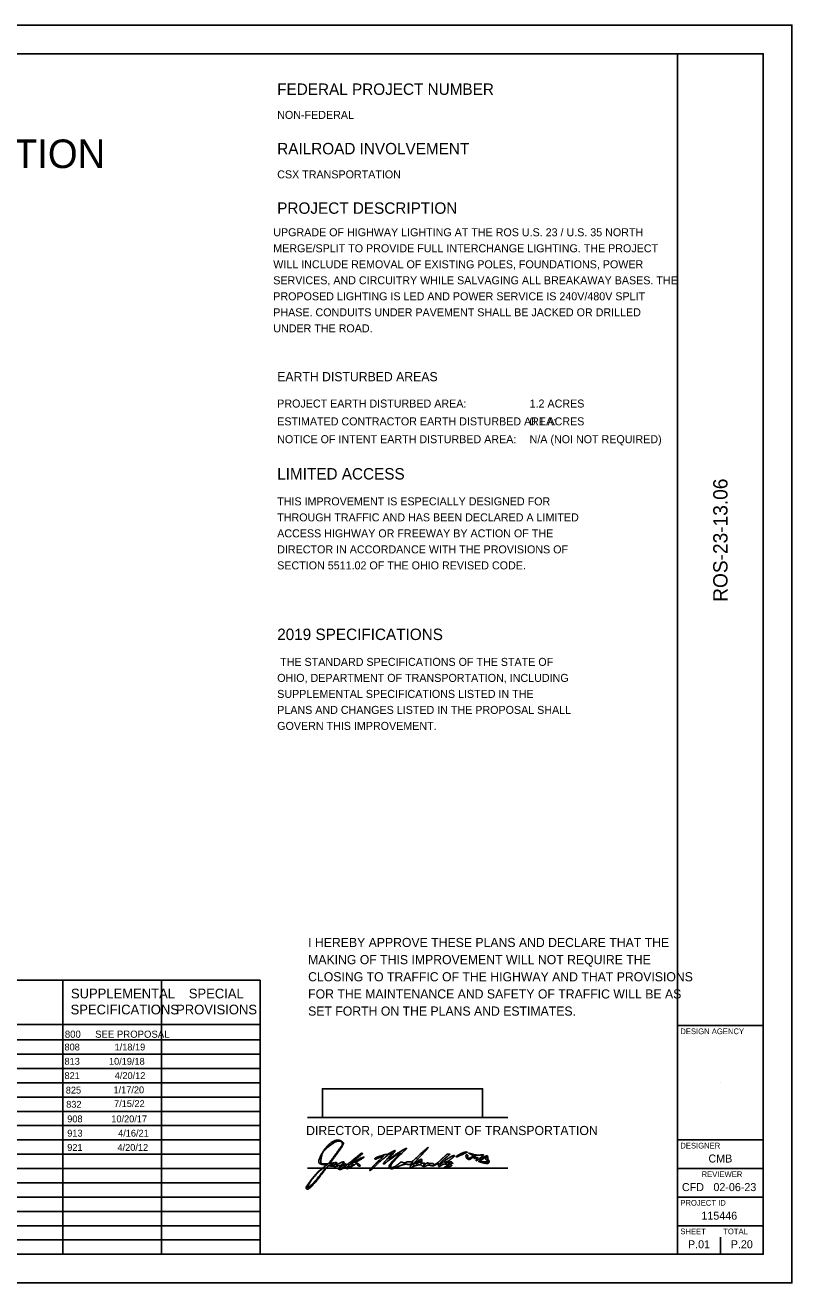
# Model space of a CAD drawing. Extents: x 0 to 51, y -1.2 to 22.
# Drawn here: x 20.59 to 34, y 0 to 22 of the extents above; entities that cross this region are included whole.
import ezdxf

# ---------------------------------------------------------------- set-up
doc = ezdxf.new("R2010")
doc.units = 0
for name, color, linetype in [('Default', 7, 'Continuous'), ('SH_Border', 7, 'Continuous'), ('SH_Cut_Line', 7, 'Continuous'), ('SH_Data', 7, 'Continuous'), ('SH_Text', 7, 'Continuous')]:
    doc.layers.add(name, color=color, linetype=linetype)

msp = doc.modelspace()

# ---------------------------------------------------------------- linework, layer by layer
at = {"layer": 'SH_Border'}
for p, q in [((32, 0.5), (32, 21.5)), ((32, 4.5), (33.5, 4.5)), ((32, 2.5), (33.5, 2.5)), ((32, 2), (33.5, 2)), ((32, 1.5), (33.5, 1.5)), ((32, 1), (33.5, 1))]:
    msp.add_line(p, q, dxfattribs=at)
msp.add_lwpolyline([(1.5, 21.5), (33.5, 21.5), (33.5, 0.5), (1.5, 0.5)], close=True, dxfattribs=at)
at = {"layer": 'SH_Cut_Line'}
msp.add_lwpolyline([(0, 0), (34, 0), (34, 22), (0, 22)], close=True, dxfattribs=at)
at = {"layer": 'SH_Data'}
for p, q in [((32.75, 3.5), (32.75, 3.5)), ((25.531, 2.892), (29.031, 2.892)), ((25.531, 2.006), (29.031, 2.006)), ((32.375, 0.675), (32.375, 0.675)), ((32.75, 0.5), (32.75, 0.8))]:
    msp.add_line(p, q, dxfattribs=at)
msp.add_lwpolyline([(25.791, 2.894), (25.791, 3.394), (28.591, 3.394), (28.591, 2.894)], close=True, dxfattribs=at)
at = {"layer": 'SH_Text'}
for p, q in [((11.25, 5.292), (24.7, 5.292)), ((21.25, 0.5), (21.25, 5.292)), ((22.975, 0.5), (22.975, 5.292)), ((24.7, 0.5), (24.7, 5.292)), ((11.25, 4.521), (24.7, 4.521)), ((11.25, 4.25), (24.7, 4.25)), ((11.25, 4), (24.7, 4)), ((11.25, 3.75), (24.7, 3.75)), ((11.25, 3.5), (24.7, 3.5)), ((11.25, 3.25), (24.7, 3.25)), ((11.25, 3), (24.7, 3)), ((11.25, 2.75), (24.7, 2.75)), ((11.25, 2.5), (24.7, 2.5)), ((11.25, 2.25), (24.7, 2.25)), ((25.993, 2.211), (25.993, 2.211)), ((28.132, 2.21), (28.132, 2.21)), ((11.25, 2), (24.7, 2)), ((26.314, 2.079), (26.314, 2.079)), ((26.358, 2.121), (26.358, 2.121)), ((26.73, 2.092), (26.73, 2.092)), ((27.507, 2.123), (27.507, 2.123)), ((28.585, 2.104), (28.585, 2.104)), ((11.25, 1.75), (24.7, 1.75)), ((11.25, 1.5), (24.7, 1.5)), ((11.25, 1.25), (24.7, 1.25)), ((11.25, 1), (24.7, 1)), ((11.25, 0.75), (24.7, 0.75))]:
    msp.add_line(p, q, dxfattribs=at)
for points in [[(28.396, 2.2), (28.433, 2.222), (28.392, 2.245)], [(25.845, 2.044), (25.876, 2.065), (25.838, 2.066)], [(26.088, 2.024), (26.11, 2.056), (26.068, 2.046)], [(27.456, 2.103), (27.426, 2.077), (27.467, 2.097)], [(28.645, 2.117), (28.701, 2.117), (28.672, 2.139)]]:
    msp.add_lwpolyline(points, dxfattribs=at)
for points in [[(25.782, 2.261), (25.868, 2.412), (26.076, 2.528), (26.142, 2.462)], [(26.133, 2.453), (26.107, 2.495), (25.981, 2.454), (25.885, 2.372)], [(25.993, 2.211), (26.114, 2.374), (26.147, 2.43), (26.133, 2.453)], [(26.142, 2.462), (26.161, 2.443), (26.161, 2.438), (26.142, 2.4)], [(25.838, 2.066), (25.74, 2.067), (25.717, 2.148), (25.782, 2.261)], [(25.885, 2.372), (25.819, 2.315), (25.78, 2.251), (25.769, 2.18)], [(25.847, 2.079), (25.894, 2.079), (25.898, 2.083), (25.993, 2.211)], [(26.027, 2.232), (25.975, 2.163), (25.932, 2.102), (25.932, 2.097)], [(26.142, 2.4), (26.131, 2.377), (26.08, 2.301), (26.027, 2.232)], [(26.372, 2.188), (26.422, 2.231), (26.468, 2.266), (26.473, 2.266)], [(26.473, 2.266), (26.498, 2.267), (26.474, 2.241), (26.389, 2.174)], [(27.005, 2.273), (26.995, 2.283), (26.785, 2.116), (26.707, 2.037)], [(26.708, 2.176), (26.708, 2.186), (26.895, 2.249), (26.911, 2.244)], [(26.73, 2.092), (26.801, 2.16), (26.857, 2.216), (26.853, 2.216)], [(26.853, 2.216), (26.85, 2.216), (26.821, 2.205), (26.789, 2.191)], [(27.145, 2.273), (27.096, 2.245), (26.907, 2.113), (26.894, 2.097)], [(26.911, 2.244), (26.916, 2.242), (26.946, 2.255), (26.977, 2.273)], [(26.927, 2.173), (26.973, 2.224), (27.008, 2.27), (27.005, 2.273)], [(27.008, 2.239), (26.98, 2.207), (26.957, 2.177), (26.957, 2.173)], [(26.957, 2.173), (26.957, 2.169), (26.993, 2.19), (27.035, 2.22)], [(26.977, 2.273), (27.055, 2.32), (27.068, 2.306), (27.008, 2.239)], [(27.171, 2.259), (27.072, 2.165), (26.982, 2.057), (26.982, 2.03)], [(27.035, 2.22), (27.116, 2.276), (27.247, 2.354), (27.263, 2.354)], [(27.08, 2.194), (27.126, 2.243), (27.155, 2.279), (27.145, 2.273)], [(27.263, 2.354), (27.268, 2.354), (27.227, 2.311), (27.171, 2.259)], [(27.315, 2.118), (27.348, 2.115), (27.372, 2.131), (27.49, 2.24)], [(27.521, 2.232), (27.391, 2.095), (27.359, 2.048), (27.441, 2.115)], [(27.49, 2.24), (27.565, 2.309), (27.631, 2.366), (27.637, 2.366)], [(27.637, 2.366), (27.642, 2.366), (27.59, 2.306), (27.521, 2.232)], [(27.97, 2.206), (27.896, 2.145), (27.845, 2.092), (27.845, 2.075)], [(27.879, 2.093), (27.933, 2.142), (28.08, 2.232), (28.097, 2.226)], [(27.898, 2.184), (27.943, 2.228), (27.98, 2.254), (27.998, 2.253)], [(27.998, 2.253), (28.022, 2.253), (28.018, 2.246), (27.97, 2.206)], [(28.097, 2.226), (28.105, 2.223), (28.09, 2.204), (28.063, 2.184)], [(28.132, 2.21), (28.132, 2.222), (28.285, 2.292), (28.304, 2.289)], [(28.204, 2.231), (28.141, 2.202), (28.132, 2.2), (28.132, 2.21)], [(28.304, 2.289), (28.325, 2.285), (28.326, 2.285), (28.204, 2.231)], [(28.333, 2.166), (28.307, 2.18), (28.296, 2.241), (28.32, 2.241)], [(28.32, 2.241), (28.327, 2.241), (28.332, 2.227), (28.332, 2.21)], [(28.332, 2.21), (28.332, 2.173), (28.347, 2.171), (28.396, 2.2)], [(28.392, 2.245), (28.349, 2.269), (28.348, 2.269), (28.451, 2.242)], [(28.456, 2.195), (28.48, 2.225), (28.464, 2.221), (28.408, 2.184)], [(28.451, 2.242), (28.472, 2.237), (28.517, 2.234), (28.551, 2.236)], [(28.551, 2.236), (28.606, 2.239), (28.611, 2.238), (28.591, 2.223)], [(28.591, 2.223), (28.562, 2.201), (28.585, 2.185), (28.619, 2.203)], [(28.653, 2.184), (28.663, 2.21), (28.654, 2.207), (28.592, 2.162)], [(28.619, 2.203), (28.659, 2.225), (28.682, 2.219), (28.682, 2.187)], [(25.838, 2.014), (25.817, 2.035), (25.599, 1.81), (25.553, 1.719)], [(25.594, 1.801), (25.672, 1.902), (25.752, 1.979), (25.845, 2.044)], [(25.623, 1.738), (25.69, 1.807), (25.846, 2.007), (25.838, 2.014)], [(25.769, 2.18), (25.757, 2.106), (25.779, 2.079), (25.847, 2.079)], [(25.927, 2.044), (25.893, 2.047), (25.881, 2.037), (25.805, 1.935)], [(25.939, 2.078), (25.916, 2.077), (25.917, 2.076), (25.943, 2.065)], [(26.068, 2.046), (26.027, 2.036), (26.005, 2.036), (25.927, 2.044)], [(25.932, 2.097), (25.932, 2.092), (25.948, 2.092), (25.967, 2.096)], [(25.982, 2.092), (25.972, 2.085), (25.952, 2.079), (25.939, 2.078)], [(25.943, 2.065), (25.973, 2.053), (26.029, 2.078), (26.011, 2.095)], [(25.967, 2.096), (25.992, 2.102), (25.996, 2.101), (25.982, 2.092)], [(26.011, 2.095), (26.007, 2.1), (26.013, 2.104), (26.025, 2.104)], [(26.025, 2.104), (26.04, 2.104), (26.045, 2.097), (26.04, 2.085)], [(26.04, 2.085), (26.031, 2.062), (26.044, 2.061), (26.076, 2.083)], [(26.087, 1.984), (26.069, 1.991), (26.069, 1.994), (26.088, 2.024)], [(26.076, 2.083), (26.105, 2.103), (26.17, 2.12), (26.17, 2.108)], [(26.154, 2.004), (26.128, 1.988), (26.098, 1.98), (26.087, 1.984)], [(26.155, 2.054), (26.104, 2.026), (26.084, 2.004), (26.111, 2.004)], [(26.111, 2.004), (26.134, 2.004), (26.26, 2.093), (26.372, 2.188)], [(26.148, 2.084), (26.129, 2.071), (26.131, 2.069), (26.164, 2.074)], [(26.17, 2.108), (26.17, 2.104), (26.16, 2.093), (26.148, 2.084)], [(26.205, 2.017), (26.202, 2.026), (26.183, 2.021), (26.154, 2.004)], [(26.164, 2.074), (26.201, 2.08), (26.201, 2.08), (26.155, 2.054)], [(26.319, 2.047), (26.25, 2.003), (26.213, 1.993), (26.205, 2.017)], [(26.26, 2.063), (26.216, 2.022), (26.227, 2.013), (26.285, 2.043)], [(26.314, 2.079), (26.296, 2.085), (26.28, 2.08), (26.26, 2.063)], [(26.389, 2.174), (26.295, 2.101), (26.274, 2.079), (26.318, 2.103)], [(26.285, 2.043), (26.332, 2.066), (26.335, 2.071), (26.314, 2.079)], [(26.318, 2.103), (26.33, 2.109), (26.354, 2.111), (26.371, 2.107)], [(26.404, 2.066), (26.387, 2.09), (26.385, 2.089), (26.319, 2.047)], [(26.362, 2.116), (26.357, 2.116), (26.356, 2.118), (26.358, 2.121)], [(26.358, 2.121), (26.379, 2.139), (26.511, 2.204), (26.516, 2.199)], [(26.516, 2.199), (26.522, 2.193), (26.38, 2.116), (26.362, 2.116)], [(26.371, 2.107), (26.407, 2.098), (26.465, 2.041), (26.439, 2.041)], [(26.439, 2.041), (26.429, 2.041), (26.413, 2.052), (26.404, 2.066)], [(26.62, 1.967), (26.61, 1.967), (26.659, 2.023), (26.73, 2.092)], [(26.707, 2.037), (26.67, 1.998), (26.63, 1.967), (26.62, 1.967)], [(26.789, 2.191), (26.726, 2.164), (26.707, 2.161), (26.708, 2.176)], [(26.861, 2.079), (26.851, 2.079), (26.88, 2.12), (26.927, 2.173)], [(26.894, 2.097), (26.886, 2.087), (26.871, 2.079), (26.861, 2.079)], [(26.973, 2.008), (26.947, 2.033), (26.976, 2.083), (27.08, 2.194)], [(27.172, 2.056), (27.026, 1.998), (26.991, 1.99), (26.973, 2.008)], [(26.982, 2.03), (26.982, 2.022), (26.99, 2.016), (27, 2.016)], [(27, 2.016), (27.022, 2.016), (27.103, 2.061), (27.14, 2.094)], [(27.14, 2.094), (27.16, 2.112), (27.173, 2.114), (27.197, 2.105)], [(27.278, 2.073), (27.249, 2.076), (27.209, 2.07), (27.172, 2.056)], [(27.197, 2.105), (27.217, 2.098), (27.236, 2.098), (27.252, 2.107)], [(27.252, 2.107), (27.265, 2.115), (27.293, 2.12), (27.315, 2.118)], [(27.347, 2.087), (27.332, 2.073), (27.31, 2.069), (27.278, 2.073)], [(27.344, 2.016), (27.326, 2.016), (27.33, 2.049), (27.351, 2.066)], [(27.362, 2.027), (27.359, 2.021), (27.351, 2.016), (27.344, 2.016)], [(27.37, 2.095), (27.37, 2.102), (27.36, 2.098), (27.347, 2.087)], [(27.351, 2.066), (27.361, 2.075), (27.37, 2.088), (27.37, 2.095)], [(27.438, 2.054), (27.4, 2.044), (27.366, 2.032), (27.362, 2.027)], [(27.523, 2.056), (27.512, 2.067), (27.492, 2.066), (27.438, 2.054)], [(27.441, 2.115), (27.49, 2.155), (27.532, 2.166), (27.532, 2.137)], [(27.507, 2.123), (27.507, 2.136), (27.483, 2.127), (27.456, 2.103)], [(27.467, 2.097), (27.489, 2.108), (27.507, 2.12), (27.507, 2.123)], [(27.517, 2.106), (27.506, 2.095), (27.512, 2.091), (27.544, 2.091)], [(27.532, 2.137), (27.532, 2.129), (27.526, 2.114), (27.517, 2.106)], [(27.619, 2.053), (27.588, 2.037), (27.54, 2.038), (27.523, 2.056)], [(27.544, 2.091), (27.581, 2.091), (27.584, 2.089), (27.568, 2.07)], [(27.568, 2.07), (27.556, 2.055), (27.563, 2.057), (27.59, 2.076)], [(27.59, 2.076), (27.611, 2.091), (27.632, 2.1), (27.636, 2.096)], [(27.684, 2.053), (27.657, 2.061), (27.634, 2.061), (27.619, 2.053)], [(27.636, 2.096), (27.64, 2.092), (27.663, 2.089), (27.688, 2.089)], [(27.773, 2.065), (27.735, 2.046), (27.717, 2.044), (27.684, 2.053)], [(27.688, 2.089), (27.712, 2.089), (27.732, 2.084), (27.732, 2.077)], [(27.732, 2.077), (27.732, 2.054), (27.828, 2.116), (27.898, 2.184)], [(27.82, 2.065), (27.82, 2.088), (27.819, 2.088), (27.773, 2.065)], [(27.882, 2.062), (27.837, 2.035), (27.82, 2.036), (27.82, 2.065)], [(27.845, 2.075), (27.845, 2.068), (27.86, 2.076), (27.879, 2.093)], [(27.965, 2.07), (27.926, 2.08), (27.909, 2.078), (27.882, 2.062)], [(28.001, 2.029), (27.954, 2.013), (27.907, 2.019), (27.951, 2.035)], [(27.973, 2.123), (27.923, 2.108), (27.943, 2.094), (27.995, 2.108)], [(27.951, 2.035), (27.965, 2.04), (27.985, 2.047), (27.995, 2.05)], [(27.995, 2.05), (28.006, 2.055), (27.995, 2.062), (27.965, 2.07)], [(28.007, 2.14), (28.004, 2.136), (27.988, 2.128), (27.973, 2.123)], [(27.995, 2.108), (28.033, 2.118), (28.048, 2.118), (28.06, 2.105)], [(28.042, 2.098), (28.005, 2.107), (27.992, 2.084), (28.026, 2.071)], [(28.026, 2.071), (28.057, 2.059), (28.048, 2.044), (28.001, 2.029)], [(28.063, 2.184), (28.036, 2.164), (28.011, 2.144), (28.007, 2.14)], [(28.06, 2.105), (28.073, 2.092), (28.07, 2.091), (28.042, 2.098)], [(28.408, 2.184), (28.368, 2.157), (28.355, 2.154), (28.333, 2.166)], [(28.475, 2.184), (28.442, 2.175), (28.44, 2.177), (28.456, 2.195)], [(28.495, 2.173), (28.51, 2.191), (28.508, 2.192), (28.475, 2.184)], [(28.524, 2.164), (28.492, 2.134), (28.469, 2.141), (28.495, 2.173)], [(28.549, 2.152), (28.58, 2.185), (28.558, 2.196), (28.524, 2.164)], [(28.585, 2.104), (28.53, 2.117), (28.524, 2.124), (28.549, 2.152)], [(28.592, 2.162), (28.549, 2.13), (28.565, 2.117), (28.645, 2.117)], [(28.703, 2.111), (28.695, 2.09), (28.654, 2.087), (28.585, 2.104)], [(28.672, 2.139), (28.652, 2.155), (28.646, 2.168), (28.653, 2.184)], [(28.682, 2.187), (28.682, 2.172), (28.689, 2.152), (28.697, 2.145)], [(28.697, 2.145), (28.704, 2.137), (28.707, 2.122), (28.703, 2.111)], [(25.805, 1.935), (25.652, 1.733), (25.507, 1.604), (25.507, 1.671)], [(25.507, 1.671), (25.507, 1.681), (25.547, 1.739), (25.594, 1.801)], [(25.553, 1.719), (25.521, 1.658), (25.553, 1.667), (25.623, 1.738)]]:
    msp.add_open_spline(points, degree=2, dxfattribs=at)

# ---------------------------------------------------------------- texts
at = {"layer": 'Default'}
for s, height, p in [('I HEREBY APPROVE THESE PLANS AND DECLARE THAT THE ', 0.16, (25.541, 5.874)), ('MAKING OF THIS IMPROVEMENT WILL NOT REQUIRE THE ', 0.16, (25.541, 5.574)), ('CLOSING TO TRAFFIC OF THE HIGHWAY AND THAT PROVISIONS ', 0.16, (25.541, 5.274)), ('FOR THE MAINTENANCE AND SAFETY OF TRAFFIC WILL BE AS ', 0.16, (25.541, 4.974)), ('SET FORTH ON THE PLANS AND ESTIMATES.', 0.16, (25.541, 4.674)), ('800', 0.125, (21.286, 4.287)), ('SEE PROPOSAL', 0.125, (21.816, 4.287))]:
    msp.add_text(s, height=height, dxfattribs=at).set_placement(p)
at = {"layer": 'SH_Data'}
for s, height, p in [('UPGRADE OF HIGHWAY LIGHTING AT THE ROS U.S. 23 / U.S. 35 NORTH', 0.14, (24.931, 18.307)), ('MERGE/SPLIT TO PROVIDE FULL INTERCHANGE LIGHTING. THE PROJECT ', 0.14, (24.931, 18.027)), ('WILL INCLUDE REMOVAL OF EXISTING POLES, FOUNDATIONS, POWER ', 0.14, (24.931, 17.747)), ('SERVICES, AND CIRCUITRY WHILE SALVAGING ALL BREAKAWAY BASES. THE ', 0.14, (24.931, 17.467)), ('PROPOSED LIGHTING IS LED AND POWER SERVICE IS 240V/480V SPLIT ', 0.14, (24.931, 17.187)), ('PHASE. CONDUITS UNDER PAVEMENT SHALL BE JACKED OR DRILLED ', 0.14, (24.931, 16.907)), ('UNDER THE ROAD. ', 0.14, (24.931, 16.627)), ('DESIGN AGENCY', 0.1, (32.05, 4.35)), ('DESIGNER', 0.1, (32.05, 2.35)), ('CMB', 0.14, (32.542, 2.105)), ('REVIEWER', 0.1, (32.422, 1.85)), ('CFD', 0.14, (32.078, 1.605)), ('02-06-23', 0.14, (32.629, 1.605)), ('PROJECT ID', 0.1, (32.05, 1.35)), ('115446', 0.14, (32.419, 1.105)), ('SHEET', 0.1, (32.05, 0.85)), ('TOTAL', 0.1, (32.8, 0.85)), ('P.01', 0.14, (32.184, 0.605)), ('P.20', 0.14, (32.932, 0.605))]:
    msp.add_text(s, height=height, dxfattribs=at).set_placement(p)
msp.add_text('ROS-23-13.06', height=0.25, rotation=90, dxfattribs=at).set_placement((32.875, 11.913))
at = {"layer": 'SH_Text'}
for s, height, p in [('FEDERAL PROJECT NUMBER', 0.2, (25, 20.78)), ('NON-FEDERAL', 0.14, (25, 20.36)), ('DEPARTMENT OF TRANSPORTATION', 0.5, (9.92, 19.5)), ('RAILROAD INVOLVEMENT', 0.2, (25, 19.74)), ('CSX TRANSPORTATION', 0.14, (25, 19.32)), ('PROJECT DESCRIPTION', 0.2, (25, 18.7)), ('EARTH DISTURBED AREAS', 0.16, (25, 15.771)), ('PROJECT EARTH DISTURBED AREA:', 0.14, (25, 15.311)), ('1.2 ACRES', 0.14, (29.414, 15.311)), ('ESTIMATED CONTRACTOR EARTH DISTURBED AREA:', 0.14, (25, 14.999)), ('0.1 ACRES', 0.14, (29.414, 14.999)), ('NOTICE OF INTENT EARTH DISTURBED AREA:', 0.14, (25, 14.687)), ('N/A (NOI NOT REQUIRED)', 0.14, (29.414, 14.687)), ('LIMITED ACCESS', 0.2, (25, 14.052)), ('THIS IMPROVEMENT IS ESPECIALLY DESIGNED FOR', 0.14, (25, 13.6)), ('THROUGH TRAFFIC AND HAS BEEN DECLARED A LIMITED', 0.14, (25, 13.32)), ('ACCESS HIGHWAY OR FREEWAY BY ACTION OF THE', 0.14, (25, 13.04)), ('DIRECTOR IN ACCORDANCE WITH THE PROVISIONS OF', 0.14, (25, 12.76)), ('SECTION 5511.02 OF THE OHIO REVISED CODE.', 0.14, (25, 12.48)), ('2019 SPECIFICATIONS', 0.2, (25, 11.244)), (' THE STANDARD SPECIFICATIONS OF THE STATE OF', 0.14, (25, 10.792)), ('OHIO, DEPARTMENT OF TRANSPORTATION, INCLUDING', 0.14, (25, 10.512)), ('SUPPLEMENTAL SPECIFICATIONS LISTED IN THE', 0.14, (25, 10.232)), ('PLANS AND CHANGES LISTED IN THE PROPOSAL SHALL', 0.14, (25, 9.952)), ('GOVERN THIS IMPROVEMENT.', 0.14, (25, 9.672)), ('SUPPLEMENTAL', 0.17, (21.393, 4.976)), ('SPECIAL', 0.17, (23.454, 4.976)), ('SPECIFICATIONS', 0.17, (21.387, 4.696)), ('PROVISIONS', 0.17, (23.232, 4.696)), ('808', 0.12, (21.28, 4.065)), ('1/18/19', 0.12, (22.156, 4.065)), ('813', 0.12, (21.28, 3.815)), ('10/19/18', 0.12, (22.058, 3.815)), ('821', 0.12, (21.28, 3.565)), ('4/20/12', 0.12, (22.159, 3.565)), ('825', 0.12, (21.303, 3.311)), ('1/17/20', 0.12, (22.137, 3.316)), ('832', 0.12, (21.31, 3.063)), ('7/15/22', 0.12, (22.147, 3.075)), ('908', 0.12, (21.328, 2.808)), ('10/20/17', 0.12, (22.099, 2.808)), ('913', 0.12, (21.328, 2.558)), ('4/16/21', 0.12, (22.218, 2.558)), ('DIRECTOR, DEPARTMENT OF TRANSPORTATION', 0.16, (25.506, 2.585)), ('921', 0.12, (21.328, 2.308)), ('4/20/12', 0.12, (22.207, 2.308))]:
    msp.add_text(s, height=height, dxfattribs=at).set_placement(p)

doc.saveas('drawing.dxf')
